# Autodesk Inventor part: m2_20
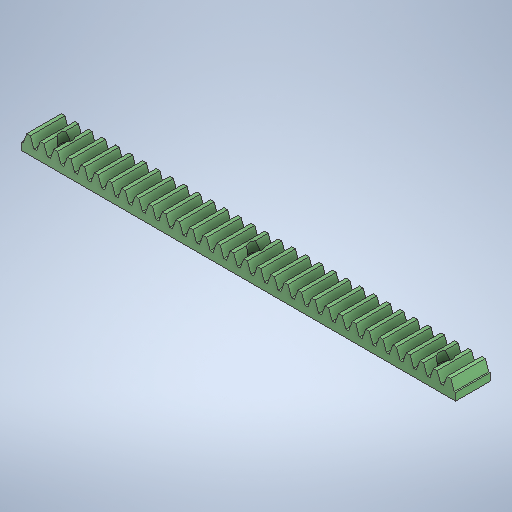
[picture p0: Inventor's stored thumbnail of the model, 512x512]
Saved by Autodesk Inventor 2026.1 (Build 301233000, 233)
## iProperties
Created: 2025-11
Part Number: m2_20
Material: Steel
Document SubType Name: Modeling
Designer: Yury Melnikov
Density: 7.85 g/cm^3
Appearance: Резина — зеленая
Sending System: Autodesk Translation Framework v14.17.0.0
Preprocessor: ST-DEVELOPER v20.1
Title: m2_20.step
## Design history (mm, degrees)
feature "Body3"
sketch "Эскиз1"
  geometry: L1 (0, 0)-(201.062, 0) reference; L2 (201.062, 0)-(201.062, 16) reference; L3 (0, 16)-(201.062, 16) reference; L4 (0, 0)-(0, 16) reference; C1 r 1.35 at (12.566, 8) reference; C2 r 1.35 at (100.531, 8) reference; C3 r 1.35 at (188.496, 8) reference; 1 further point
  dimensions: "d0" = 87.96459 distance of C2.centre C1.centre (derived); "d1" = 12.56644 distance from line of L4 C1.centre (derived); "d2" = 201.062 distance of L3.start L2.end (derived); "d3" = 16 distance of L1.start L3.start (derived); "d4" = 12.56637 distance from line of L2 C3.centre (derived)
  node "Спроецированная петля1"
node "Твердое тело1"
